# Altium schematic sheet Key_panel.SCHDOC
size B
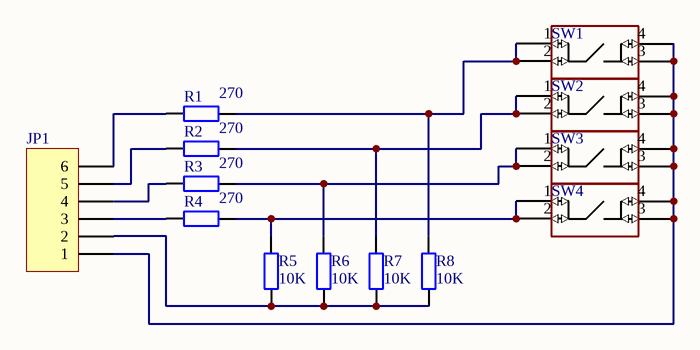
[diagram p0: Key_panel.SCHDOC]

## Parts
JP1  Header 6  [HDR1X6]  (value not drawn)
R1  value 270  [C3216-1206]  (hidden comment: Res2)
R2  value 270  [C3216-1206]  (hidden comment: Res2)
R3  value 270  [C3216-1206]  (hidden comment: Res2)
R4  value 270  [C3216-1206]  (hidden comment: Res2)
R5  value 10K  [C3216-1206]  (hidden comment: Res2)
R6  value 10K  [C3216-1206]  (hidden comment: Res2)
R7  value 10K  [C3216-1206]  (hidden comment: Res2)
R8  value 10K  [C3216-1206]  (hidden comment: Res2)
SW1  Push Button  [PushButton]  (value not drawn)
SW2  Push Button  [PushButton]  (value not drawn)
SW3  Push Button  [PushButton]  (value not drawn)
SW4  Push Button  [PushButton]  (value not drawn)

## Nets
NetJP1_1: JP1.1 SW1.3 SW1.4 SW2.3 SW2.4 SW3.3 SW3.4 SW4.3 SW4.4
NetJP1_2: JP1.2 R5.1 R6.1 R7.1 R8.1
NetJP1_3: JP1.3 R4.1
NetJP1_4: JP1.4 R3.1
NetJP1_5: JP1.5 R2.1
NetJP1_6: JP1.6 R1.1
NetR1_2: R1.2 R8.2 SW1.1 SW1.2
NetR2_2: R2.2 R7.2 SW2.1 SW2.2
NetR3_2: R3.2 R6.2 SW3.1 SW3.2
NetR4_2: R4.2 R5.2 SW4.1 SW4.2

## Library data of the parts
JP1 = Header 6: Header, 6-Pin; Manufacturer: Generic Components; Class: Connector
R1-R8 = Res2: Resistor; Manufacturer: Generic Components; Class: Passive
SW1-SW4 = PUSHBUTTON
